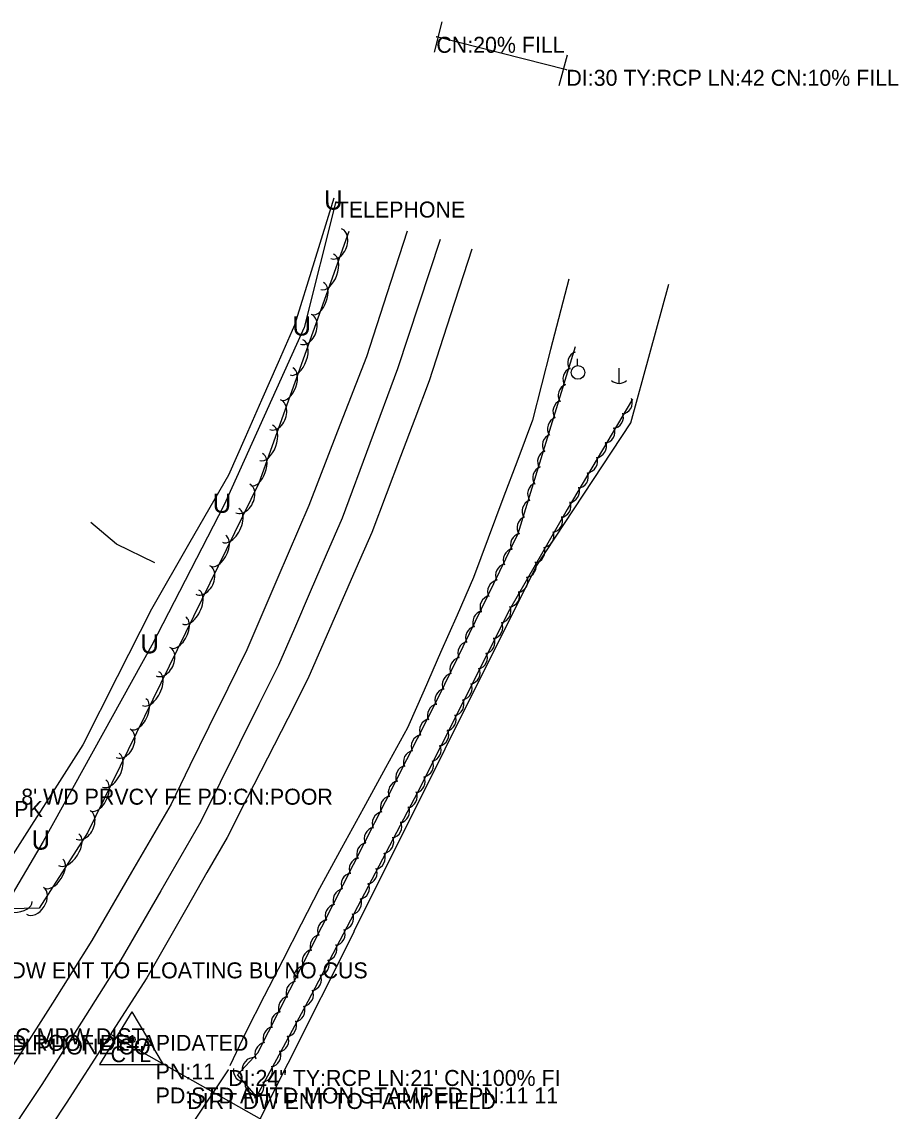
# Model space of a CAD drawing. Extents: x 1451369 to 1458940, y 1868647 to 1875095.
# Drawn here: x 1455092.6 to 1455366.9, y 1872324.4 to 1872665.3 of the extents above; entities that cross this region are included whole.
import ezdxf

# ---------------------------------------------------------------- set-up
doc = ezdxf.new("R2010")
doc.units = 0
for name, color, linetype in [('Default', 7, 'Continuous'), ('E_Const Align', 7, 'Continuous'), ('E_PL and Hook', 7, 'Continuous'), ('E_Proposed ROW and Easements', 7, 'Continuous'), ('E_ROW Point Number', 7, 'Continuous'), ('E_Survey Point Number', 7, 'Continuous'), ('E_Tract Number', 7, 'Continuous'), ('R_No Plot', 7, 'Continuous'), ('S_BUILDING_ANNOT', 7, 'Continuous'), ('S_CROSS_DRAIN', 7, 'Continuous'), ('S_CROSS_DRAIN_ANNOT', 7, 'Continuous'), ('S_EDGE_PAVEMENT', 7, 'Continuous'), ('S_EXIST_ROW', 7, 'Continuous'), ('S_FENCE_ANNOT', 7, 'Continuous'), ('S_HEADWALL', 7, 'Continuous'), ('S_IRON_PIN_ANNOT', 7, 'Continuous'), ('S_MISC_BOUNDARY', 7, 'Continuous'), ('S_PAVEMENT_CROWN', 7, 'Continuous'), ('S_PRIMARY_CTL_ANNOT', 7, 'Continuous'), ('S_SIDE_DRAIN_ANNOT', 7, 'Continuous'), ('S_SURVEY_TEXT_ANNOT', 7, 'Continuous'), ('S_TELEPHONE_UTILITIES_ANNOT', 7, 'Continuous'), ('S_TRAILS', 7, 'Continuous'), ('S_UNDERGROUND_CABLE_ANNOT', 7, 'Continuous')]:
    doc.layers.add(name, color=color, linetype=linetype)

msp = doc.modelspace()

# ---------------------------------------------------------------- linework, layer by layer
at = {"layer": 'E_Const Align'}
for p, q in [((1455266.52, 1872557.73), (1455266.52, 1872559.83)), ((1455279.46, 1872556.87), (1455279.46, 1872552.14))]:
    msp.add_line(p, q, dxfattribs=at)
msp.add_circle((1455266.64, 1872555.58), 2.13, dxfattribs=at)
msp.add_arc((1455279.52, 1872555.57), 3.41, 226.3972, 313.6028, dxfattribs=at)
at = {"layer": 'E_PL and Hook'}
msp.add_line((1455157.21, 1872337.28), (1455145.4, 1872319.72), dxfattribs=at)
at = {"layer": 'E_Proposed ROW and Easements'}
msp.add_lwpolyline([(1455144.4, 1872330.08), (1455144.4, 1872330.13), (1455144.4, 1872330.08), (1455144.35, 1872330.08), (1455144.4, 1872330.08), (1455144.4, 1872330.03), (1455144.4, 1872330.08), (1455144.45, 1872330.08)], dxfattribs=at)
at = {"layer": 'E_ROW Point Number'}
for points in [[(1455194.92, 1872599.73), (1455166.83, 1872520.95), (1455113.21, 1872411.5), (1455098.05, 1872387.88), (1455079.09, 1872387.5)], [(1455283.73, 1872547.25), (1455263.27, 1872512.7), (1455245.22, 1872481.31), (1455216.53, 1872424.29), (1455182.11, 1872358.76), (1455166.11, 1872329.02), (1455160.08, 1872335.79), (1455166.46, 1872342.69), (1455223.11, 1872454.16), (1455247.92, 1872505.15), (1455265.92, 1872563.71)]]:
    msp.add_lwpolyline(points, dxfattribs=at)
for centre, major_axis, ratio, start_param, end_param in [((1455191.01, 1872595.86), (1.67, 4.66), 0.685666, 3.142266, 6.283859), ((1455188.15, 1872587.06), (1.97, 5.52), 0.550365, 3.142004, 6.283596), ((1455185.18, 1872578.71), (1.8, 5.03), 0.54098, 3.141991, 6.283583), ((1455181.47, 1872569.1), (1.67, 4.66), 0.685666, 3.142266, 6.283859), ((1455178.61, 1872560.3), (1.97, 5.52), 0.550365, 3.142004, 6.283596), ((1455267.1, 1872558.59), (-1.07, -3.48), 0.999303, 3.825789, 5.598989), ((1455175.63, 1872551.95), (1.8, 5.03), 0.54098, 3.141991, 6.283583), ((1455265.57, 1872553.51), (-1.07, -3.48), 0.999303, 3.825789, 5.598989), ((1455264.09, 1872548.44), (-1.07, -3.48), 0.999303, 3.825789, 5.598989), ((1455171.93, 1872542.34), (1.67, 4.66), 0.685666, 3.142266, 6.283859), ((1455280, 1872546.18), (1.86, 3.14), 0.999276, 3.825789, 5.598989), ((1455262.45, 1872543.36), (-1.07, -3.48), 0.999303, 3.825789, 5.598989), ((1455260.76, 1872537.98), (-1.07, -3.48), 0.999303, 3.825789, 5.598989), ((1455277.22, 1872541.62), (1.86, 3.14), 0.999276, 3.825789, 5.598989), ((1455169.07, 1872533.54), (1.97, 5.52), 0.550365, 3.142004, 6.283596), ((1455274.59, 1872537.04), (1.86, 3.14), 0.999276, 3.825789, 5.598989), ((1455259.16, 1872532.78), (-1.07, -3.48), 0.999303, 3.825789, 5.598989), ((1455271.92, 1872532.46), (1.86, 3.14), 0.999276, 3.825789, 5.598989), ((1455166.09, 1872525.19), (1.8, 5.03), 0.54098, 3.141991, 6.283583), ((1455257.64, 1872527.7), (-1.07, -3.48), 0.999303, 3.825789, 5.598989), ((1455269.15, 1872527.78), (1.86, 3.14), 0.999276, 3.825789, 5.598989), ((1455256.15, 1872522.63), (-1.07, -3.48), 0.999303, 3.825789, 5.598989), ((1455266.24, 1872522.94), (1.86, 3.14), 0.999276, 3.825789, 5.598989), ((1455161.81, 1872516.12), (2.18, 4.45), 0.685336, 3.141291, 6.282884), ((1455254.52, 1872517.55), (-1.07, -3.48), 0.999303, 3.825789, 5.598989), ((1455263.46, 1872518.38), (1.86, 3.14), 0.999276, 3.825789, 5.598989), ((1455157.97, 1872507.69), (2.58, 5.27), 0.5501, 3.141408, 6.283001), ((1455252.82, 1872512.16), (-1.07, -3.48), 0.999303, 3.825789, 5.598989), ((1455260.82, 1872513.77), (1.82, 3.16), 0.999276, 3.825789, 5.598989), ((1455251.22, 1872506.96), (-1.07, -3.48), 0.999303, 3.825789, 5.598989), ((1455258.21, 1872509.15), (1.82, 3.16), 0.999276, 3.825789, 5.598989), ((1455154.07, 1872499.73), (2.35, 4.8), 0.540719, 3.141414, 6.283007), ((1455249.17, 1872501.64), (-1.59, -3.28), 0.999276, 3.825789, 5.598989), ((1455255.49, 1872504.44), (1.82, 3.16), 0.999276, 3.825789, 5.598989), ((1455246.93, 1872496.86), (-1.59, -3.28), 0.999276, 3.825789, 5.598989), ((1455252.65, 1872499.56), (1.82, 3.16), 0.999276, 3.825789, 5.598989), ((1455249.93, 1872494.97), (1.82, 3.16), 0.999276, 3.825789, 5.598989), ((1455149.3, 1872490.59), (2.18, 4.45), 0.685336, 3.141291, 6.282884), ((1455244.53, 1872492.1), (-1.59, -3.28), 0.999276, 3.825789, 5.598989), ((1455242.03, 1872487.03), (-1.59, -3.28), 0.999276, 3.825789, 5.598989), ((1455247.36, 1872490.35), (1.82, 3.16), 0.999276, 3.825789, 5.598989), ((1455145.47, 1872482.16), (2.58, 5.27), 0.5501, 3.141408, 6.283001), ((1455239.64, 1872482.14), (-1.59, -3.28), 0.999276, 3.825789, 5.598989), ((1455244.74, 1872485.74), (1.82, 3.16), 0.999276, 3.825789, 5.598989), ((1455242.05, 1872480.84), (1.64, 3.25), 0.999276, 3.825789, 5.598989), ((1455141.57, 1872474.2), (2.35, 4.8), 0.540719, 3.141414, 6.283007), ((1455237.36, 1872477.36), (-1.59, -3.28), 0.999276, 3.825789, 5.598989), ((1455235.11, 1872472.58), (-1.59, -3.28), 0.999276, 3.825789, 5.598989), ((1455239.48, 1872475.81), (1.64, 3.25), 0.999276, 3.825789, 5.598989), ((1455237.02, 1872471.08), (1.64, 3.25), 0.999276, 3.825789, 5.598989), ((1455136.8, 1872465.06), (2.18, 4.45), 0.685336, 3.141291, 6.282884), ((1455232.71, 1872467.81), (-1.59, -3.28), 0.999276, 3.825789, 5.598989), ((1455230.21, 1872462.75), (-1.59, -3.28), 0.999276, 3.825789, 5.598989), ((1455234.71, 1872466.33), (1.64, 3.25), 0.999276, 3.825789, 5.598989), ((1455132.96, 1872456.64), (2.58, 5.27), 0.5501, 3.141408, 6.283001), ((1455232.36, 1872461.58), (1.64, 3.25), 0.999276, 3.825789, 5.598989), ((1455227.83, 1872457.86), (-1.59, -3.28), 0.999276, 3.825789, 5.598989), ((1455225.54, 1872453.07), (-1.59, -3.28), 0.999276, 3.825789, 5.598989), ((1455229.91, 1872456.72), (1.64, 3.25), 0.999276, 3.825789, 5.598989), ((1455129.06, 1872448.67), (2.35, 4.8), 0.540719, 3.141414, 6.283007), ((1455223.19, 1872448.29), (-2.21, -2.9), 0.999251, 4.007034, 5.780234), ((1455227.34, 1872451.69), (1.64, 3.25), 0.999276, 3.825789, 5.598989), ((1455224.88, 1872446.96), (1.64, 3.25), 0.999276, 3.825789, 5.598989), ((1455220.71, 1872443.56), (-2.21, -2.9), 0.999251, 4.007034, 5.780234), ((1455124.3, 1872439.54), (2.18, 4.45), 0.685336, 3.141291, 6.282884), ((1455218.12, 1872438.55), (-2.21, -2.9), 0.999251, 4.007034, 5.780234), ((1455222.57, 1872442.2), (1.64, 3.25), 0.999276, 3.825789, 5.598989), ((1455220.22, 1872437.45), (1.64, 3.25), 0.999276, 3.825789, 5.598989), ((1455120.46, 1872431.11), (2.58, 5.27), 0.5501, 3.141408, 6.283001), ((1455215.65, 1872433.7), (-2.21, -2.9), 0.999251, 4.007034, 5.780234), ((1455213.28, 1872428.95), (-2.21, -2.9), 0.999251, 4.007034, 5.780234), ((1455217.77, 1872432.59), (1.64, 3.25), 0.999276, 3.825789, 5.598989), ((1455116.56, 1872423.15), (2.35, 4.8), 0.540719, 3.141414, 6.283007), ((1455210.95, 1872424.21), (-2.21, -2.9), 0.999251, 4.007034, 5.780234), ((1455215.2, 1872427.56), (1.64, 3.25), 0.999276, 3.825789, 5.598989), ((1455212.71, 1872422.9), (1.69, 3.23), 0.999275, 3.825789, 5.598989), ((1455208.47, 1872419.49), (-2.21, -2.9), 0.999251, 4.007034, 5.780234), ((1455111.79, 1872414.01), (2.18, 4.45), 0.685336, 3.141291, 6.282884), ((1455205.89, 1872414.47), (-2.21, -2.9), 0.999251, 4.007034, 5.780234), ((1455210.32, 1872418.19), (1.69, 3.23), 0.999275, 3.825789, 5.598989), ((1455207.88, 1872413.47), (1.69, 3.23), 0.999275, 3.825789, 5.598989), ((1455107.31, 1872406.22), (3.17, 4.94), 0.550031, 3.141593, 6.283185), ((1455203.42, 1872409.62), (-2.21, -2.9), 0.999251, 4.007034, 5.780234), ((1455201.05, 1872404.87), (-2.21, -2.9), 0.999251, 4.007034, 5.780234), ((1455205.35, 1872408.66), (1.69, 3.23), 0.999275, 3.825789, 5.598989), ((1455202.7, 1872403.67), (1.69, 3.23), 0.999275, 3.825789, 5.598989), ((1455102.52, 1872398.76), (2.89, 4.5), 0.540651, 3.141593, 6.283185), ((1455198.72, 1872400.13), (-2.21, -2.9), 0.999251, 4.007034, 5.780234), ((1455200.15, 1872398.98), (1.69, 3.23), 0.999275, 3.825789, 5.598989), ((1455196.24, 1872395.41), (-2.21, -2.9), 0.999251, 4.007034, 5.780234), ((1455096.73, 1872390.23), (2.68, 4.17), 0.68525, 3.141593, 6.283185), ((1455193.65, 1872390.39), (-2.21, -2.9), 0.999251, 4.007034, 5.780234), ((1455197.76, 1872394.27), (1.69, 3.23), 0.999275, 3.825789, 5.598989), ((1455195.32, 1872389.56), (1.69, 3.23), 0.999275, 3.825789, 5.598989), ((1455090.02, 1872389.84), (5.87, 0.12), 0.550087, 3.141588, 6.28318), ((1455191.18, 1872385.54), (-2.21, -2.9), 0.999251, 4.007034, 5.780234), ((1455188.81, 1872380.8), (-2.21, -2.9), 0.999251, 4.007034, 5.780234), ((1455192.79, 1872384.75), (1.69, 3.23), 0.999275, 3.825789, 5.598989), ((1455190.13, 1872379.76), (1.69, 3.23), 0.999275, 3.825789, 5.598989), ((1455186.48, 1872376.05), (-2.21, -2.9), 0.999251, 4.007034, 5.780234), ((1455184, 1872371.33), (-2.21, -2.9), 0.999251, 4.007034, 5.780234), ((1455187.59, 1872375.07), (1.69, 3.23), 0.999275, 3.825789, 5.598989), ((1455181.41, 1872366.31), (-2.21, -2.9), 0.999251, 4.007034, 5.780234), ((1455185.2, 1872370.36), (1.69, 3.23), 0.999275, 3.825789, 5.598989), ((1455182.76, 1872365.65), (1.69, 3.23), 0.999275, 3.825789, 5.598989), ((1455178.94, 1872361.46), (-2.21, -2.9), 0.999251, 4.007034, 5.780234), ((1455176.57, 1872356.72), (-2.21, -2.9), 0.999251, 4.007034, 5.780234), ((1455180.23, 1872360.83), (1.69, 3.23), 0.999275, 3.825789, 5.598989), ((1455177.55, 1872355.9), (1.73, 3.21), 0.999275, 3.825789, 5.598989), ((1455174.24, 1872351.98), (-2.21, -2.9), 0.999251, 4.007034, 5.780234), ((1455171.76, 1872347.25), (-2.21, -2.9), 0.999251, 4.007034, 5.780234), ((1455174.95, 1872351.23), (1.73, 3.21), 0.999275, 3.825789, 5.598989), ((1455172.52, 1872346.55), (1.73, 3.21), 0.999275, 3.825789, 5.598989), ((1455169.18, 1872342.24), (-2.21, -2.9), 0.999251, 4.007034, 5.780234), ((1455170.04, 1872341.86), (1.73, 3.21), 0.999275, 3.825789, 5.598989), ((1455165.25, 1872337.52), (-2.47, -2.68), 0.99932, 3.825789, 5.598989), ((1455162.42, 1872337.17), (1.87, -3.12), 0.999912, 4.012991, 5.786192), ((1455167.46, 1872337.07), (1.73, 3.21), 0.999275, 3.825789, 5.598989), ((1455165.99, 1872333.27), (1.87, -3.12), 0.999912, 4.012991, 5.786192), ((1455164.75, 1872332.11), (1.73, 3.21), 0.999275, 3.825789, 5.598989)]:
    msp.add_ellipse(centre, major_axis=major_axis, ratio=ratio, start_param=start_param, end_param=end_param, dxfattribs=at)
at = {"layer": 'E_Survey Point Number'}
for p, q in [((1455190.85, 1872609.06), (1455180.93, 1872569.66)), ((1455180.93, 1872569.66), (1455155.98, 1872514.17)), ((1455155.98, 1872514.17), (1455133.36, 1872470.22)), ((1455133.36, 1872470.22), (1455099.32, 1872408.78)), ((1455099.32, 1872408.78), (1455087.55, 1872388.74))]:
    msp.add_line(p, q, dxfattribs=at)
at = {"layer": 'E_Tract Number'}
for points in [[(1455222.34, 1872660.61), (1455222.34, 1872660.66), (1455222.34, 1872660.61), (1455222.29, 1872660.61), (1455222.34, 1872660.61), (1455222.34, 1872660.56), (1455222.34, 1872660.61), (1455222.39, 1872660.61)], [(1455263.03, 1872650.29), (1455263.03, 1872650.34), (1455263.03, 1872650.29), (1455262.98, 1872650.29), (1455263.03, 1872650.29), (1455263.03, 1872650.24), (1455263.03, 1872650.29), (1455263.08, 1872650.29)], [(1455157.21, 1872337.28), (1455157.21, 1872337.33), (1455157.21, 1872337.28), (1455157.16, 1872337.28), (1455157.21, 1872337.28), (1455157.21, 1872337.23), (1455157.21, 1872337.28), (1455157.26, 1872337.28)]]:
    msp.add_lwpolyline(points, dxfattribs=at)
at = {"layer": 'R_No Plot'}
for p, q in [((1455127.01, 1872355.51), (1455116.97, 1872339)), ((1455127.01, 1872355.51), (1455136.83, 1872339)), ((1455116.97, 1872339), (1455136.83, 1872339))]:
    msp.add_line(p, q, dxfattribs=at)
for radius in [1.04, 0.609, 0.344]:
    msp.add_circle((1455127.01, 1872346.81), radius, dxfattribs=at)
at = {"layer": 'S_CROSS_DRAIN'}
msp.add_line((1455263.03, 1872650.29), (1455222.34, 1872660.61), dxfattribs=at)
at = {"layer": 'S_EDGE_PAVEMENT'}
for points in [[(1455213.17, 1872599.83), (1455206.82, 1872580.17), (1455200.46, 1872560.51), (1455191.43, 1872537.24), (1455182.4, 1872513.97), (1455172.69, 1872491.36), (1455162.99, 1872468.75), (1455157.08, 1872456.69), (1455151.17, 1872444.64), (1455145.25, 1872432.58), (1455139.34, 1872420.52), (1455126.92, 1872399.17), (1455114.51, 1872377.81), (1455102.18, 1872358.23), (1455089.86, 1872338.64), (1455082.86, 1872328.15), (1455075.85, 1872317.66)], [(1455233.48, 1872594.2), (1455226.79, 1872573.57), (1455220.09, 1872552.95), (1455215.6, 1872541.1), (1455211.11, 1872529.24), (1455206.62, 1872517.39), (1455202.12, 1872505.53), (1455197.13, 1872494.07), (1455192.14, 1872482.6), (1455187.14, 1872471.13), (1455182.15, 1872459.67), (1455175.82, 1872447.25), (1455169.49, 1872434.84), (1455163.16, 1872422.43), (1455156.83, 1872410.02), (1455150.56, 1872399.05), (1455144.28, 1872388.07), (1455138.01, 1872377.1), (1455131.74, 1872366.13), (1455119.14, 1872346.5), (1455106.55, 1872326.88), (1455092.89, 1872306.29)]]:
    msp.add_lwpolyline(points, dxfattribs=at)
at = {"layer": 'S_EXIST_ROW'}
for points in [[(1455190.29, 1872610.09), (1455184.14, 1872590.23), (1455178, 1872570.37), (1455172.83, 1872558.64), (1455167.67, 1872546.91), (1455162.5, 1872535.18), (1455157.33, 1872523.45), (1455145.25, 1872502.49), (1455133.16, 1872481.53), (1455122.44, 1872460.28), (1455111.71, 1872439.03), (1455103.69, 1872426.44), (1455095.67, 1872413.86), (1455087.65, 1872401.27), (1455079.63, 1872388.69)], [(1455263.8, 1872584.79), (1455258.09, 1872562.72), (1455252.38, 1872540.66), (1455247.78, 1872528.36), (1455243.19, 1872516.05), (1455238.59, 1872503.75), (1455234, 1872491.45), (1455228.84, 1872479.67), (1455223.67, 1872467.9), (1455218.51, 1872456.13), (1455213.34, 1872444.36), (1455206.44, 1872431.8), (1455199.54, 1872419.24), (1455192.64, 1872406.68), (1455185.74, 1872394.12), (1455179.99, 1872382.87), (1455174.25, 1872371.62), (1455168.5, 1872360.37), (1455162.76, 1872349.12), (1455157.67, 1872338.59)], [(1455134.23, 1872495.96), (1455122.29, 1872501.8), (1455114.22, 1872508.63)]]:
    msp.add_lwpolyline(points, dxfattribs=at)
at = {"layer": 'S_HEADWALL'}
for points in [[(1455221.73, 1872655.85), (1455224.13, 1872665.32)], [(1455263.26, 1872654.89), (1455260.64, 1872645.3)]]:
    msp.add_lwpolyline(points, dxfattribs=at)
at = {"layer": 'S_MISC_BOUNDARY'}
for points in [[(1455196.58, 1872380.69), (1455253.58, 1872494.9), (1455283.14, 1872539.81), (1455295.07, 1872583.24)], [(1454968.19, 1871712.29), (1454955.87, 1871795.22), (1454948.77, 1871830.35), (1454936.8, 1871870.9), (1454929.34, 1871910.01), (1454929.36, 1871947.22), (1454941.55, 1871984.39), (1454964.58, 1872028.21), (1455009.26, 1872095.69), (1455071.49, 1872183.66), (1455110.31, 1872228.42), (1455136.38, 1872254.42), (1455148.95, 1872271.07), (1455155.24, 1872298.12), (1455196.69, 1872380.74)]]:
    msp.add_lwpolyline(points, dxfattribs=at)
at = {"layer": 'S_PAVEMENT_CROWN'}
msp.add_lwpolyline([(1455223.54, 1872597.22), (1455216.89, 1872576.98), (1455210.23, 1872556.74), (1455201.54, 1872533.38), (1455192.85, 1872510.02), (1455187.87, 1872498.49), (1455182.88, 1872486.97), (1455177.9, 1872475.44), (1455172.92, 1872463.92), (1455166.84, 1872451.69), (1455160.76, 1872439.46), (1455154.69, 1872427.23), (1455148.61, 1872415), (1455136.12, 1872393.36), (1455123.63, 1872371.72), (1455111.27, 1872352.25), (1455098.91, 1872332.78), (1455085.14, 1872312.19)], dxfattribs=at)
at = {"layer": 'S_TRAILS'}
msp.add_lwpolyline([(1455120.4, 1872348.51), (1455167.63, 1872321.76)], dxfattribs=at)

# ---------------------------------------------------------------- texts
at = {"layer": 'Default'}
for p in [(1455187.22, 1872606.52), (1455177.3, 1872567.12), (1455152.35, 1872511.63), (1455129.73, 1872467.67), (1455095.69, 1872406.23)]:
    msp.add_text('U', height=6, rotation=360, dxfattribs=at).set_placement(p)
at = {"layer": 'R_No Plot'}
msp.add_text('CTL', height=5, rotation=360, dxfattribs=at).set_placement((1455120.42, 1872339.74))
at = {"layer": 'S_BUILDING_ANNOT'}
msp.add_text('1STRY TIN W/WD ROOF DELAPIDATED', height=5, dxfattribs=at).set_placement((1455038.7, 1872343.28))
at = {"layer": 'S_CROSS_DRAIN_ANNOT'}
for s, p in [('CN:20% FILL', (1455222.34, 1872655.61)), ('DI:30 TY:RCP LN:42 CN:10% FILL', (1455263.03, 1872645.29))]:
    msp.add_text(s, height=5, dxfattribs=at).set_placement(p)
at = {"layer": 'S_FENCE_ANNOT'}
msp.add_text("8' WD PRVCY FE PD:CN:POOR", height=5, dxfattribs=at).set_placement((1455092.45, 1872420.31))
at = {"layer": 'S_IRON_PIN_ANNOT'}
msp.add_text('5X5 CONC MRW DIST', height=5, dxfattribs=at).set_placement((1455061.98, 1872345.32))
at = {"layer": 'S_PRIMARY_CTL_ANNOT'}
for s, p in [('PN:11', (1455134.51, 1872334.31)), ('PD:STD AHTD MON STAMPED PN:11 11', (1455134.51, 1872326.81))]:
    msp.add_text(s, height=5, dxfattribs=at).set_placement(p)
at = {"layer": 'S_SIDE_DRAIN_ANNOT'}
msp.add_text('DI:24" TY:RCP LN:21\' CN:100% FI', height=5, dxfattribs=at).set_placement((1455157.21, 1872332.28))
at = {"layer": 'S_SURVEY_TEXT_ANNOT'}
for s, p in [('GRVL PK', (1455070.2, 1872416.47)), ('GR DW ENT TO FLOATING BU NO CUS', (1455077.15, 1872365.96)), ('DIRT DW ENT TO FARM FIELD', (1455144.4, 1872325.08))]:
    msp.add_text(s, height=5, dxfattribs=at).set_placement(p)
at = {"layer": 'S_TELEPHONE_UTILITIES_ANNOT'}
msp.add_text('GENERAL TELPHONE CO', height=5, dxfattribs=at).set_placement((1455051.18, 1872342.13))
at = {"layer": 'S_UNDERGROUND_CABLE_ANNOT'}
msp.add_text('TELEPHONE', height=5, dxfattribs=at).set_placement((1455190.85, 1872604.06))

doc.saveas('drawing.dxf')
